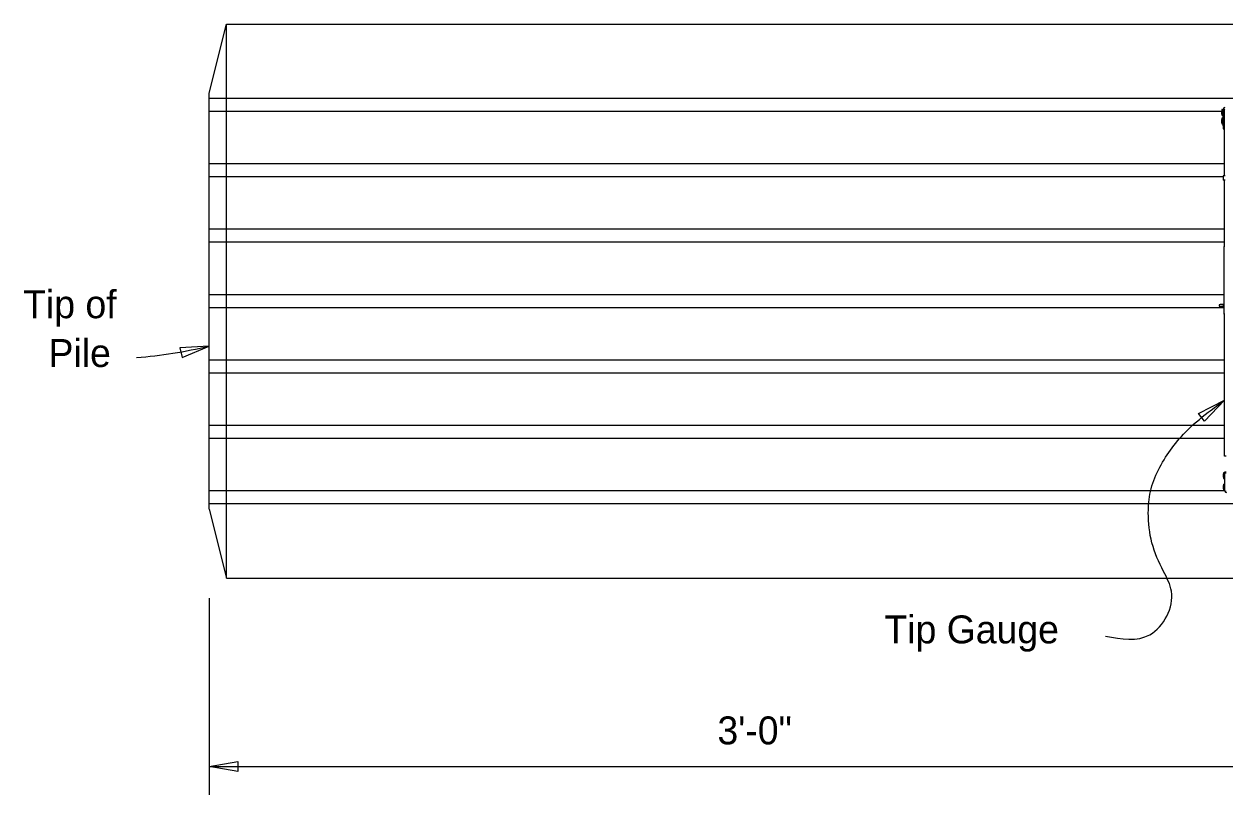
# Model space of a CAD drawing. Extents: x 0 to 36.1, y -3.7 to 15.
# Drawn here: x 0.111 to 4.444, y 9.588 to 12.369 of the extents above; entities that cross this region are included whole.
import ezdxf

# ---------------------------------------------------------------- set-up
doc = ezdxf.new("R2010")
doc.units = 0
for name, color, linetype in [('Dimension', 7, 'Continuous'), ('Leader', 7, 'Continuous'), ('Miscellaneous', 7, 'Continuous'), ('PileConc', 7, 'Continuous'), ('PrestressSteel', 7, 'Continuous'), ('TextStructures', 7, 'Continuous')]:
    doc.layers.add(name, color=color, linetype=linetype)

msp = doc.modelspace()

# ---------------------------------------------------------------- linework, layer by layer
at = {"layer": 'Dimension'}
for p, q in [((0.7785, 10.2978), (0.7785, 9.5876)), ((0.7785, 9.6904), (4.7785, 9.6904))]:
    msp.add_line(p, q, dxfattribs=at)
for points in [[(0.7785, 11.2073), (0.6731, 11.2005), (0.6812, 11.1661)], [(4.4432, 11.0125), (4.3703, 10.9361), (4.3492, 10.9644)], [(0.7785, 9.6904), (0.8826, 9.7081), (0.8826, 9.6728)]]:
    msp.add_lwpolyline(points, close=True, dxfattribs=at)
at = {"layer": 'Leader'}
msp.add_arc((0.366, 12.948), 1.7889, 274.8384, 283.331, dxfattribs=at)
msp.add_spline([(4.0139, 10.1601), (4.1735, 10.1659), (4.2515, 10.3224), (4.2227, 10.3942), (4.1811, 10.4973), (4.1679, 10.6058), (4.1758, 10.6826), (4.2479, 10.8321), (4.3017, 10.8967), (4.3843, 10.9685), (4.4432, 11.0125)], degree=3, dxfattribs=at)
at = {"layer": 'Miscellaneous'}
for p, q in [((4.433, 12.0598), (4.433, 12.0503)), ((4.433, 12.0503), (4.433, 12.0408)), ((4.4342, 12.0607), (4.4382, 12.0607)), ((4.4342, 12.0607), (4.4342, 12.0503)), ((4.4342, 12.0503), (4.4342, 12.0399)), ((4.4432, 12.0621), (4.4382, 12.0621)), ((4.4382, 12.0017), (4.4382, 12.0621)), ((4.4432, 12.0621), (4.4445, 12.0621)), ((4.4432, 12.0017), (4.4432, 12.0621)), ((4.433, 12.0285), (4.433, 12.019)), ((4.433, 12.019), (4.433, 12.0095)), ((4.4382, 12.0399), (4.4342, 12.0399)), ((4.4342, 12.0294), (4.4382, 12.0294)), ((4.4342, 12.0294), (4.4342, 12.019)), ((4.4342, 12.019), (4.4342, 12.0085)), ((4.4382, 12.0085), (4.4342, 12.0085)), ((4.4432, 12.0017), (4.4382, 12.0017)), ((4.4382, 12.0017), (4.4382, 11.9912)), ((4.4382, 11.9912), (4.4432, 11.9912)), ((4.4432, 11.9912), (4.4432, 12.0017)), ((4.4432, 11.822), (4.4432, 11.9916)), ((4.4382, 11.822), (4.4382, 11.8064)), ((4.4447, 11.822), (4.4382, 11.822)), ((4.4447, 11.8064), (4.4382, 11.8064)), ((4.4432, 11.5665), (4.4432, 11.8064)), ((4.4407, 11.5665), (4.4407, 11.3225)), ((4.4445, 11.5665), (4.4407, 11.5665)), ((4.436, 11.3577), (4.4268, 11.3577)), ((4.4403, 11.3577), (4.436, 11.3577)), ((4.4403, 11.3499), (4.4403, 11.3577)), ((4.4403, 11.3577), (4.4407, 11.3577)), ((4.436, 11.3499), (4.4268, 11.3499)), ((4.4403, 11.3499), (4.436, 11.3499)), ((4.4403, 11.3499), (4.4407, 11.3499)), ((4.4445, 11.3225), (4.4407, 11.3225)), ((4.4432, 10.8099), (4.4432, 11.3225)), ((4.4485, 10.8099), (4.4432, 10.8099)), ((4.4392, 10.7494), (4.4392, 10.7304)), ((4.4404, 10.7503), (4.4445, 10.7503)), ((4.4404, 10.7503), (4.4404, 10.7295)), ((4.4445, 10.7537), (4.4485, 10.7537)), ((4.4445, 10.7487), (4.4445, 10.7537)), ((4.4485, 10.7487), (4.4445, 10.7487)), ((4.4445, 10.6843), (4.4445, 10.7487)), ((4.4392, 10.7304), (4.4392, 10.7304)), ((4.4392, 10.7076), (4.4392, 10.6963)), ((4.4404, 10.7295), (4.4404, 10.7294)), ((4.4445, 10.7294), (4.4404, 10.7294)), ((4.4404, 10.7085), (4.4445, 10.7085)), ((4.4404, 10.7085), (4.4404, 10.6961)), ((4.4392, 10.6963), (4.4392, 10.6886)), ((4.4404, 10.6961), (4.4404, 10.6877)), ((4.4445, 10.6877), (4.4404, 10.6877)), ((4.4445, 10.6843), (4.4485, 10.6843))]:
    msp.add_line(p, q, dxfattribs=at)
msp.add_lwpolyline([(4.436, 11.3499), (4.4373, 11.3502), (4.4384, 11.3511), (4.4391, 11.3523), (4.4393, 11.3538), (4.4391, 11.3553), (4.4384, 11.3566), (4.4373, 11.3574), (4.436, 11.3577)], dxfattribs=at)
for centre, radius, start, end in [((4.4685, 12.0503), 0.0367, 164.9997, 195.0003), ((4.4342, 12.0595), 0.00125, 90, 164.9997), ((4.4445, 12.0621), 0.00625, 90, 180), ((4.4445, 12.0621), 0.00125, 90, 180), ((4.4685, 12.019), 0.0367, 164.9997, 195.0003), ((4.4342, 12.0411), 0.00125, 195.0003, 270), ((4.4342, 12.0282), 0.00125, 90, 164.9997), ((4.4342, 12.0098), 0.00125, 195.0003, 270), ((4.4268, 11.3538), 0.00388, 90, 270), ((4.4747, 10.7399), 0.0367, 164.9997, 195.0003), ((4.4404, 10.749), 0.00125, 90, 164.9997), ((4.4747, 10.6981), 0.0367, 164.9997, 195.0003), ((4.4404, 10.7307), 0.00125, 195.0003, 270), ((4.4404, 10.7073), 0.00125, 90, 164.9997), ((4.4404, 10.6889), 0.00125, 195.0003, 270), ((4.4497, 10.6843), 0.00526, 180, 270)]:
    msp.add_arc(centre, radius, start, end, dxfattribs=at)
at = {"layer": 'PileConc'}
for p, q in [((0.7785, 12.1193), (0.841, 12.3693)), ((0.841, 10.3693), (0.841, 12.3693)), ((0.841, 12.3693), (10.1834, 12.3693)), ((0.7785, 10.6193), (0.7785, 12.1193)), ((0.7785, 10.6193), (0.841, 10.3693)), ((0.841, 10.3693), (10.1834, 10.3693))]:
    msp.add_line(p, q, dxfattribs=at)
at = {"layer": 'PrestressSteel'}
for p, q in [((10.1834, 12.1005), (0.7785, 12.1005)), ((4.4319, 12.0536), (0.7785, 12.0536)), ((4.4432, 11.8645), (0.7785, 11.8645)), ((4.4382, 11.8176), (0.7785, 11.8176)), ((4.4432, 11.6286), (0.7785, 11.6286)), ((4.4432, 11.5817), (0.7785, 11.5817)), ((4.4407, 11.3927), (0.7785, 11.3927)), ((4.4407, 11.3458), (0.7785, 11.3458)), ((4.4432, 11.1568), (0.7785, 11.1568)), ((4.4432, 11.1099), (0.7785, 11.1099)), ((4.4432, 10.9208), (0.7785, 10.9208)), ((4.4432, 10.8739), (0.7785, 10.8739)), ((4.4445, 10.685), (0.7785, 10.685)), ((10.1834, 10.6381), (0.7785, 10.6381))]:
    msp.add_line(p, q, dxfattribs=at)

# ---------------------------------------------------------------- texts
at = {"layer": 'Dimension'}
for s, p in [('Tip of', (0.1079, 11.3078)), ('Pile', (0.1995, 11.1318)), ('Tip Gauge', (3.2158, 10.1346))]:
    msp.add_text(s, height=0.1008, dxfattribs=at).set_placement(p)
at = {"layer": 'TextStructures'}
msp.add_text('3\'-0"', height=0.1008, dxfattribs=at).set_placement((2.6131, 9.7702))

doc.saveas('drawing.dxf')
